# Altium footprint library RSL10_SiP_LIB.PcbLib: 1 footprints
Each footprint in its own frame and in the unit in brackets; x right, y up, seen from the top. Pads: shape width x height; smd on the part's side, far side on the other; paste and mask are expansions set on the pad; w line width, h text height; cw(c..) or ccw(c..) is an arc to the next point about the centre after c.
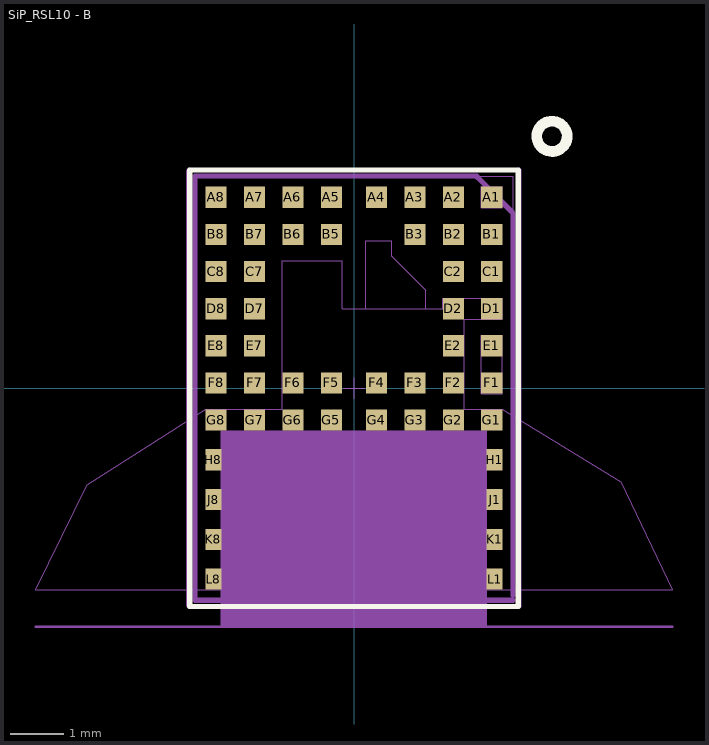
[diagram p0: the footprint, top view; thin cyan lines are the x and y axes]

## SiP_RSL10 - B [mm] "SiP Module"
height 1.7
pads (51):
  rect 0.4x0.4 smd mask+0.05: A1(2.6,3.6) A2(1.875,3.6) A3(1.15,3.6) A4(0.425,3.6) A5(-0.425,3.6) A6(-1.15,3.6) A7(-1.875,3.6) A8(-2.6,3.6) B1(2.6,2.9) B2(1.875,2.9) B3(1.15,2.9) B5(-0.425,2.9) B6(-1.15,2.9) B7(-1.875,2.9) B8(-2.6,2.9) C1(2.6,2.2) C2(1.875,2.2) C7(-1.875,2.2) C8(-2.6,2.2) D1(2.6,1.5) D2(1.875,1.5) D7(-1.875,1.5) D8(-2.6,1.5) E1(2.6,0.8) E2(1.875,0.8) E7(-1.875,0.8) E8(-2.6,0.8) F1(2.6,0.1) F2(1.875,0.1) F3(1.15,0.1) F4(0.425,0.1) F5(-0.425,0.1) F6(-1.15,0.1) F7(-1.875,0.1) F8(-2.6,0.1) G1(2.6,-0.6) G2(1.875,-0.6) G3(1.15,-0.6) G4(0.425,-0.6) G5(-0.425,-0.6) G6(-1.15,-0.6) G7(-1.875,-0.6) G8(-2.6,-0.6)
  rect 0.3x0.4 smd mask+0.05: H1(2.65,-1.35) H8(-2.65,-1.35) J1(2.65,-2.1) J8(-2.65,-2.1) K1(2.65,-2.85) K8(-2.65,-2.85) L1(2.65,-3.6) L8(-2.65,-3.6)
Top Overlay 1:
  lines w0.1: -3.099,-4.115 3.099,-4.115 3.099,4.115 -3.099,4.115 -3.099,-4.115
  lines w0.2: 4.019,4.777 ccw(c3.734,4.75) 4.02,4.763
Mechanical 1:
  pour cut-out: -2.5,-0.8 -2.5,-4.47 2.5,-4.47 2.5,-0.8
  lines w0.01: -2.5,-0.813 -2.5,-4.47 2.5,-4.47
  lines w0.013: -2.5,-0.8 2.5,-0.8 2.5,-4.47
  text "Area void of" at -1.727,-2.134 h0.3
  text "copper" at -0.965,-2.769 h0.3
  text "on all layers" at -1.753,-3.48 h0.3
Mechanical 2:
  lines w0.013: -3,4 3,4 ; -3,4 -3,-4 3,-4 ; 3,-4 3,4 ; 3,-4 3,4
Mechanical 3:
  lines w0.013: 0.225,1.5 1.35,1.5 1.35,1.847 0.708,2.489 0.708,2.782 0.225,2.782 0.225,1.5
  text "on top layer" at 1.27,1.956 h0.3
  text "Area void of copper" at 1.295,2.362 h0.3
Mechanical 4:
  lines w0.013: -2.8,-0.4 -5.031,-1.822 -6,-3.8 -2.5,-3.8 -2.5,-0.8 2.5,-0.8 2.5,-3.8 6,-3.8 5.026,-1.763 2.8,-0.4 2.075,-0.4 2.075,1.3 2.8,1.3 2.8,1.7 1.675,1.7 1.675,1.5 -0.225,1.5 -0.225,2.4 -1.35,2.4 -1.35,-0.4 -2.794,-0.4 ; 2.4,-0.1 2.4,1 2.8,1 2.8,-0.1 2.4,-0.1
  text "gnd plane shown" at 3.226,-2.692 h0.3
  text "Partial" at 3.226,-2.159 h0.3
Mechanical 8:
  lines w0.013: -3,-4 3,-4 3,4 -3,4 -3,-4
Mechanical 10:
  lines w0.05: -6,-4.5 6,-4.5
  text "Board edge" at -1.702,-4.877 h0.3
Mechanical 11:
  lines w0.013: -0.2,0 0.2,0 ; 0,-0.2 0,0.2
Mechanical 13:
  lines w0.013: -3.15,-4.1 ccw(c-3.1,-4.1) -3.1,-4.15 3.1,-4.15 ccw(c3.1,-4.1) 3.15,-4.1 3.15,4.1 ccw(c3.1,4.1) 3.1,4.15 -3.1,4.15 ccw(c-3.1,4.1) -3.15,4.1 -3.15,-4.1
Mechanical 15:
  lines w0.013: 2.4,3.4 2.8,3.4 2.8,3.8 2.4,3.8 2.4,3.4
  lines w0.1: -2.997,3.988 -2.997,-4 3,-4 ; -2.997,4 2.317,4 ; 2.317,3.988 2.99,3.314 ; 3,-3.906 3,3.282
  text "'.Designator'" at -1.575,0.502 h1
Mechanical 18:
  lines w0.013: -6,-3.8 -6,-3.8 ; 6,-3.8 6,-3.8
3D body "RSL10SIP.stp": height 1.22, standoff -0.25, extent -3.009,-4.015 2.997,3.988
